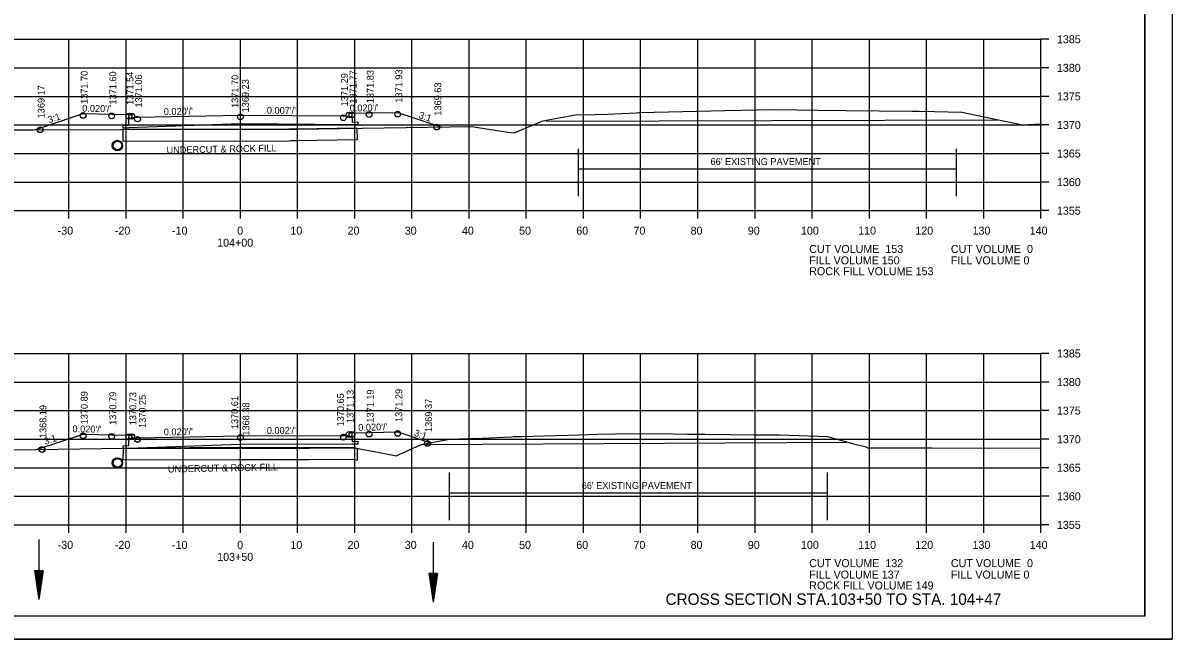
# Model space of a CAD drawing. Extents: x 1374311 to 1383814, y 384102 to 406278.
# Drawn here: x 1382682.8 to 1382883.8, y 385332.6 to 385440.4 of the extents above; entities that cross this region are included whole.
import ezdxf

# ---------------------------------------------------------------- set-up
doc = ezdxf.new("R2010")
doc.units = 0
for name, color, linetype in [('R_Axis', 7, 'Continuous'), ('R_Axis Annot', 7, 'Continuous'), ('R_Border', 7, 'Continuous'), ('R_Draft', 7, 'Continuous'), ('R_Exist Surface', 7, 'Continuous'), ('R_Fin Surface', 7, 'Continuous'), ('R_Grid', 7, 'Continuous'), ('R_No Plot', 7, 'Continuous'), ('R_Water', 7, 'Continuous'), ('R_Xsect Elev', 7, 'Continuous'), ('R_Xsect Slope', 7, 'Continuous')]:
    doc.layers.add(name, color=color, linetype=linetype)

msp = doc.modelspace()

# ---------------------------------------------------------------- linework, layer by layer
at = {"layer": 'R_Axis'}
for p, q in [((1382860.86, 385407.55), (1382860.86, 385437.55)), ((1382862.26, 385437.55), (1382860.86, 385437.55)), ((1382862.26, 385432.55), (1382860.86, 385432.55)), ((1382862.26, 385427.55), (1382860.86, 385427.55)), ((1382862.26, 385422.55), (1382860.86, 385422.55)), ((1382862.26, 385417.55), (1382860.86, 385417.55)), ((1382862.26, 385412.55), (1382860.86, 385412.55)), ((1382580.86, 385407.55), (1382860.86, 385407.55)), ((1382690.86, 385406.15), (1382690.86, 385407.55)), ((1382700.86, 385406.15), (1382700.86, 385407.55)), ((1382710.86, 385406.15), (1382710.86, 385407.55)), ((1382720.86, 385406.15), (1382720.86, 385407.55)), ((1382730.86, 385406.15), (1382730.86, 385407.55)), ((1382740.86, 385406.15), (1382740.86, 385407.55)), ((1382750.86, 385406.15), (1382750.86, 385407.55)), ((1382760.86, 385406.15), (1382760.86, 385407.55)), ((1382770.86, 385406.15), (1382770.86, 385407.55)), ((1382780.86, 385406.15), (1382780.86, 385407.55)), ((1382790.86, 385406.15), (1382790.86, 385407.55)), ((1382800.86, 385406.15), (1382800.86, 385407.55)), ((1382810.86, 385406.15), (1382810.86, 385407.55)), ((1382820.86, 385406.15), (1382820.86, 385407.55)), ((1382830.86, 385406.15), (1382830.86, 385407.55)), ((1382840.86, 385406.15), (1382840.86, 385407.55)), ((1382850.86, 385406.15), (1382850.86, 385407.55)), ((1382860.86, 385406.15), (1382860.86, 385407.55)), ((1382862.26, 385407.55), (1382860.86, 385407.55)), ((1382860.86, 385352.55), (1382860.86, 385382.55)), ((1382862.26, 385382.55), (1382860.86, 385382.55)), ((1382862.26, 385377.55), (1382860.86, 385377.55)), ((1382862.26, 385372.55), (1382860.86, 385372.55)), ((1382862.26, 385367.55), (1382860.86, 385367.55)), ((1382862.26, 385362.55), (1382860.86, 385362.55)), ((1382862.26, 385357.55), (1382860.86, 385357.55)), ((1382580.86, 385352.55), (1382860.86, 385352.55)), ((1382690.86, 385351.15), (1382690.86, 385352.55)), ((1382700.86, 385351.15), (1382700.86, 385352.55)), ((1382710.86, 385351.15), (1382710.86, 385352.55)), ((1382720.86, 385351.15), (1382720.86, 385352.55)), ((1382730.86, 385351.15), (1382730.86, 385352.55)), ((1382740.86, 385351.15), (1382740.86, 385352.55)), ((1382750.86, 385351.15), (1382750.86, 385352.55)), ((1382760.86, 385351.15), (1382760.86, 385352.55)), ((1382770.86, 385351.15), (1382770.86, 385352.55)), ((1382780.86, 385351.15), (1382780.86, 385352.55)), ((1382790.86, 385351.15), (1382790.86, 385352.55)), ((1382800.86, 385351.15), (1382800.86, 385352.55)), ((1382810.86, 385351.15), (1382810.86, 385352.55)), ((1382820.86, 385351.15), (1382820.86, 385352.55)), ((1382830.86, 385351.15), (1382830.86, 385352.55)), ((1382840.86, 385351.15), (1382840.86, 385352.55)), ((1382850.86, 385351.15), (1382850.86, 385352.55)), ((1382860.86, 385351.15), (1382860.86, 385352.55)), ((1382862.26, 385352.55), (1382860.86, 385352.55))]:
    msp.add_line(p, q, dxfattribs=at)
at = {"layer": 'R_Border'}
for q in [(1382879.04, 385542.01), (1382562.86, 385336.55)]:
    msp.add_line((1382879.04, 385336.55), q, dxfattribs=at)
at = {"layer": 'R_Draft'}
for p, q in [((1382684.84, 385344.5), (1382685.59, 385339.5)), ((1382686.34, 385344.5), (1382684.84, 385344.5)), ((1382684.97, 385344.5), (1382685.59, 385340.34)), ((1382685.1, 385344.5), (1382685.59, 385341.2)), ((1382685.22, 385344.5), (1382685.59, 385342.03)), ((1382685.35, 385344.5), (1382685.59, 385342.88)), ((1382685.48, 385344.5), (1382685.59, 385343.71)), ((1382686.34, 385344.5), (1382685.59, 385339.5)), ((1382685.84, 385344.5), (1382685.59, 385342.88)), ((1382686.09, 385344.5), (1382685.59, 385341.2)), ((1382686.22, 385344.5), (1382685.59, 385340.34)), ((1382685.97, 385344.5), (1382685.59, 385342.03)), ((1382685.71, 385344.5), (1382685.59, 385343.71)), ((1382753.83, 385344.03), (1382754.58, 385339.03)), ((1382755.33, 385344.03), (1382753.83, 385344.03)), ((1382753.96, 385344.03), (1382754.58, 385339.86)), ((1382754.09, 385344.03), (1382754.58, 385340.72)), ((1382754.21, 385344.03), (1382754.58, 385341.56)), ((1382754.34, 385344.03), (1382754.58, 385342.4)), ((1382754.47, 385344.03), (1382754.58, 385343.24)), ((1382755.33, 385344.03), (1382754.58, 385339.03)), ((1382754.83, 385344.03), (1382754.58, 385342.4)), ((1382755.08, 385344.03), (1382754.58, 385340.72)), ((1382755.21, 385344.03), (1382754.58, 385339.86)), ((1382754.96, 385344.03), (1382754.58, 385341.56)), ((1382754.7, 385344.03), (1382754.58, 385343.24))]:
    msp.add_line(p, q, dxfattribs=at)
at = {"layer": 'R_Exist Surface'}
for points in [[(1382669.63, 385421.71), (1382684.55, 385421.72), (1382699.89, 385421.74), (1382729.33, 385421.8), (1382729.62, 385421.81), (1382730.65, 385421.83), (1382761.33, 385422.27), (1382767.64, 385421.3), (1382768.72, 385421.17), (1382773.37, 385423.11), (1382773.77, 385423.29), (1382774.35, 385423.4), (1382779.44, 385424.32), (1382782.88, 385424.39), (1382785.08, 385424.46), (1382790.09, 385424.69), (1382790.56, 385424.71), (1382790.75, 385424.72), (1382805.57, 385425.1), (1382808.37, 385425.14), (1382813.91, 385425.23), (1382818.32, 385425.18), (1382821.86, 385425.13), (1382826.79, 385425.09), (1382838.29, 385424.97), (1382839.55, 385424.94), (1382842.28, 385424.89), (1382847.03, 385424.81), (1382853.45, 385423.46), (1382857.63, 385422.56), (1382860.86, 385422.74)], [(1382665.82, 385365.44), (1382692.76, 385365.84), (1382700.33, 385365.95), (1382711.04, 385365.98), (1382725.06, 385365.92), (1382740.83, 385366.03), (1382745.16, 385365.21), (1382748.12, 385364.66), (1382751.71, 385366.25), (1382752.52, 385366.6), (1382753.08, 385366.72), (1382757.45, 385367.58), (1382760.87, 385367.68), (1382763.13, 385367.75), (1382768.32, 385367.99), (1382768.6, 385368), (1382768.99, 385368.01), (1382770.07, 385368.04), (1382780.06, 385368.33), (1382783.33, 385368.42), (1382786.47, 385368.46), (1382791.39, 385368.53), (1382796.54, 385368.48), (1382799.05, 385368.45), (1382802.14, 385368.42), (1382810.69, 385368.34), (1382813.97, 385368.31), (1382815.15, 385368.29), (1382816.85, 385368.24), (1382823.56, 385368.04), (1382827.93, 385366.79), (1382830.32, 385366.21), (1382830.58, 385366.02), (1382832.09, 385366.04), (1382833.45, 385366.03), (1382841.84, 385366.02), (1382860.86, 385365.99)]]:
    msp.add_lwpolyline(points, dxfattribs=at)
for centre in [(1382699.35, 385418.95), (1382699.35, 385363.39)]:
    msp.add_circle(centre, 0.917, dxfattribs=at)
at = {"layer": 'R_Fin Surface'}
msp.add_line((1382741.31, 385421.98), (1382730.65, 385421.83), dxfattribs=at)
for points in [[(1382684.9, 385421.72), (1382693.35, 385424.53), (1382698.35, 385424.43), (1382701.35, 385424.37), (1382701.85, 385424.37), (1382701.86, 385423.87), (1382702.86, 385423.89), (1382720.86, 385424.25), (1382738.86, 385424.12), (1382739.86, 385424.1), (1382739.87, 385424.6), (1382740.37, 385424.6), (1382743.37, 385424.66), (1382748.37, 385424.76), (1382756.08, 385422.19)], [(1382740.37, 385424.3), (1382740.38, 385423.06), (1382741.38, 385423.08), (1382741.37, 385422.58), (1382740.37, 385422.59), (1382720.86, 385422.73), (1382701.35, 385422.03), (1382700.35, 385422), (1382700.36, 385422.5), (1382701.36, 385422.51), (1382701.35, 385424.07)], [(1382700.31, 385421.74), (1382700.31, 385419.74), (1382729.34, 385419.8), (1382729.65, 385419.81), (1382730.68, 385419.83), (1382741.32, 385419.98), (1382741.31, 385421.98)], [(1382700.31, 385421.74), (1382700.31, 385419.74), (1382729.34, 385419.8), (1382729.65, 385419.81), (1382730.68, 385419.83), (1382741.32, 385419.98), (1382741.31, 385421.98)], [(1382730.65, 385421.83), (1382729.62, 385421.81), (1382729.33, 385421.8), (1382700.31, 385421.74)], [(1382685.21, 385365.73), (1382693.35, 385368.44), (1382698.35, 385368.34), (1382701.35, 385368.28), (1382701.85, 385368.28), (1382701.86, 385367.78), (1382702.86, 385367.8), (1382720.86, 385368.16), (1382738.86, 385368.2), (1382739.86, 385368.18), (1382739.87, 385368.68), (1382740.37, 385368.68), (1382743.37, 385368.74), (1382748.37, 385368.84), (1382754.13, 385366.92)], [(1382740.37, 385368.38), (1382740.38, 385367.16), (1382741.38, 385367.18), (1382741.37, 385366.68), (1382740.37, 385366.68), (1382720.86, 385366.63), (1382701.35, 385365.94), (1382700.35, 385365.9), (1382700.36, 385366.4), (1382701.36, 385366.42), (1382701.35, 385367.97)], [(1382700.35, 385365.95), (1382700.31, 385363.95), (1382711.04, 385363.98), (1382725.06, 385363.92), (1382740.65, 385364.03), (1382741.32, 385363.9), (1382741.35, 385365.87)]]:
    msp.add_lwpolyline(points, dxfattribs=at)
msp.add_lwpolyline([(1382700.35, 385365.9), (1382700.31, 385363.95), (1382740.65, 385364.03), (1382741.32, 385363.9), (1382741.35, 385365.87), (1382740.83, 385366.03), (1382712.01, 385366.06), (1382700.35, 385365.9)], close=True, dxfattribs=at)
at = {"layer": 'R_Grid'}
for p, q in [((1382580.86, 385437.55), (1382860.86, 385437.55)), ((1382690.86, 385407.55), (1382690.86, 385437.55)), ((1382700.86, 385407.55), (1382700.86, 385437.55)), ((1382710.86, 385407.55), (1382710.86, 385437.55)), ((1382720.86, 385407.55), (1382720.86, 385437.55)), ((1382730.86, 385407.55), (1382730.86, 385437.55)), ((1382740.86, 385407.55), (1382740.86, 385437.55)), ((1382750.86, 385407.55), (1382750.86, 385437.55)), ((1382760.86, 385407.55), (1382760.86, 385437.55)), ((1382770.86, 385407.55), (1382770.86, 385437.55)), ((1382780.86, 385407.55), (1382780.86, 385437.55)), ((1382790.86, 385407.55), (1382790.86, 385437.55)), ((1382800.86, 385407.55), (1382800.86, 385437.55)), ((1382810.86, 385407.55), (1382810.86, 385437.55)), ((1382820.86, 385407.55), (1382820.86, 385437.55)), ((1382830.86, 385407.55), (1382830.86, 385437.55)), ((1382840.86, 385407.55), (1382840.86, 385437.55)), ((1382850.86, 385407.55), (1382850.86, 385437.55)), ((1382860.86, 385407.55), (1382860.86, 385437.55)), ((1382580.86, 385432.55), (1382860.86, 385432.55)), ((1382580.86, 385427.55), (1382860.86, 385427.55)), ((1382580.86, 385422.55), (1382860.86, 385422.55)), ((1382580.86, 385417.55), (1382860.86, 385417.55)), ((1382580.86, 385412.55), (1382860.86, 385412.55)), ((1382580.86, 385407.55), (1382860.86, 385407.55)), ((1382580.86, 385382.55), (1382860.86, 385382.55)), ((1382690.86, 385352.55), (1382690.86, 385382.55)), ((1382700.86, 385352.55), (1382700.86, 385382.55)), ((1382710.86, 385352.55), (1382710.86, 385382.55)), ((1382720.86, 385352.55), (1382720.86, 385382.55)), ((1382730.86, 385352.55), (1382730.86, 385382.55)), ((1382740.86, 385352.55), (1382740.86, 385382.55)), ((1382750.86, 385352.55), (1382750.86, 385382.55)), ((1382760.86, 385352.55), (1382760.86, 385382.55)), ((1382770.86, 385352.55), (1382770.86, 385382.55)), ((1382780.86, 385352.55), (1382780.86, 385382.55)), ((1382790.86, 385352.55), (1382790.86, 385382.55)), ((1382800.86, 385352.55), (1382800.86, 385382.55)), ((1382810.86, 385352.55), (1382810.86, 385382.55)), ((1382820.86, 385352.55), (1382820.86, 385382.55)), ((1382830.86, 385352.55), (1382830.86, 385382.55)), ((1382840.86, 385352.55), (1382840.86, 385382.55)), ((1382850.86, 385352.55), (1382850.86, 385382.55)), ((1382860.86, 385352.55), (1382860.86, 385382.55)), ((1382580.86, 385377.55), (1382860.86, 385377.55)), ((1382580.86, 385372.55), (1382860.86, 385372.55)), ((1382580.86, 385367.55), (1382860.86, 385367.55)), ((1382580.86, 385362.55), (1382860.86, 385362.55)), ((1382580.86, 385357.55), (1382860.86, 385357.55)), ((1382580.86, 385352.55), (1382860.86, 385352.55))]:
    msp.add_line(p, q, dxfattribs=at)
at = {"layer": 'R_No Plot'}
msp.add_line((1382550.46, 385332.57), (1382883.79, 385332.57), dxfattribs=at)
for points in [[(1382550.45, 385545.91), (1382883.79, 385545.91), (1382883.79, 385332.57), (1382550.45, 385332.57)], [(1382796.78, 385542.01), (1382796.78, 385532.13), (1382832.51, 385532.13), (1382832.51, 385529.21), (1382855.71, 385529.21), (1382855.71, 385506), (1382879.04, 385506), (1382879.04, 385336.55), (1382562.86, 385336.55), (1382562.86, 385542.01)], [(1382700.35, 385365.9), (1382700.35, 385365.95), (1382701.76, 385365.95), (1382701.35, 385365.94)]]:
    msp.add_lwpolyline(points, close=True, dxfattribs=at)
for centre in [(1382693.35, 385424.23), (1382693.35, 385424.23), (1382698.35, 385424.13), (1382698.35, 385424.13), (1382739.87, 385424.3), (1382739.87, 385424.3), (1382740.37, 385424.3), (1382743.37, 385424.36), (1382743.37, 385424.36), (1382748.37, 385424.46), (1382748.37, 385424.46), (1382701.35, 385424.07), (1382701.85, 385424.07), (1382701.85, 385424.07), (1382702.86, 385423.59), (1382702.86, 385423.59), (1382720.86, 385423.95), (1382720.86, 385423.95), (1382738.86, 385423.82), (1382738.86, 385423.82), (1382755.2, 385422.18), (1382755.21, 385422.18), (1382685.82, 385421.72), (1382685.82, 385421.72), (1382685.82, 385421.72), (1382685.82, 385421.72), (1382693.35, 385368.15), (1382693.35, 385368.13), (1382698.35, 385368.05), (1382698.35, 385368.03), (1382701.35, 385367.97), (1382701.85, 385367.99), (1382701.85, 385367.97), (1382720.86, 385367.87), (1382738.86, 385367.91), (1382738.86, 385367.9), (1382739.87, 385368.39), (1382739.87, 385368.38), (1382740.37, 385368.38), (1382743.37, 385368.45), (1382743.37, 385368.44), (1382748.37, 385368.55), (1382748.37, 385368.54), (1382702.86, 385367.51), (1382702.86, 385367.49), (1382720.86, 385367.85), (1382753.56, 385366.81), (1382753.58, 385366.81), (1382686.13, 385365.74), (1382686.13, 385365.74), (1382686.17, 385365.74), (1382686.17, 385365.74)]:
    msp.add_circle(centre, 0.5, dxfattribs=at)
at = {"layer": 'R_Water'}
for p, q in [((1382774.31, 385423.23), (1382853.28, 385423.43)), ((1382779.98, 385410.07), (1382779.98, 385418.4)), ((1382846.08, 385410.07), (1382846.08, 385418.4)), ((1382779.98, 385414.87), (1382846.08, 385414.87)), ((1382752.52, 385366.6), (1382826.9, 385367.04)), ((1382757.45, 385353.38), (1382757.45, 385361.7)), ((1382823.56, 385353.38), (1382823.56, 385361.7)), ((1382757.45, 385358.17), (1382823.56, 385358.17)), ((1382685.59, 385350.01), (1382685.59, 385339.5)), ((1382754.58, 385349.54), (1382754.58, 385339.03))]:
    msp.add_line(p, q, dxfattribs=at)
for centre in [(1382699.35, 385418.95), (1382699.35, 385363.39)]:
    msp.add_circle(centre, 0.75, dxfattribs=at)

# ---------------------------------------------------------------- texts
at = {"layer": 'R_Axis Annot'}
for s, p in [('1385', (1382863.66, 385436.85)), ('1380', (1382863.66, 385431.85)), ('1375', (1382863.66, 385426.85)), ('1370', (1382863.66, 385421.85)), ('1365', (1382863.66, 385416.85)), ('1360', (1382863.66, 385411.85)), ('1355', (1382863.66, 385406.85)), ('-30', (1382688.9, 385403.35)), ('-20', (1382698.9, 385403.35)), ('-10', (1382708.9, 385403.35)), ('0', (1382720.3, 385403.35)), ('10', (1382729.6, 385403.35)), ('20', (1382739.6, 385403.35)), ('30', (1382749.6, 385403.35)), ('40', (1382759.6, 385403.35)), ('50', (1382769.6, 385403.35)), ('60', (1382779.6, 385403.35)), ('70', (1382789.6, 385403.35)), ('80', (1382799.6, 385403.35)), ('90', (1382809.6, 385403.35)), ('100', (1382818.9, 385403.35)), ('110', (1382828.9, 385403.35)), ('120', (1382838.9, 385403.35)), ('130', (1382848.9, 385403.35)), ('140', (1382858.9, 385403.35)), ('104+00', (1382716.8, 385401.25)), ('CUT VOLUME  153', (1382820.34, 385400.15)), ('CUT VOLUME  0', (1382845.12, 385400.15)), ('FILL VOLUME 150', (1382820.34, 385398.15)), ('FILL VOLUME 0', (1382845.12, 385398.15)), ('ROCK FILL VOLUME 153', (1382820.34, 385396.25)), ('1385', (1382863.66, 385381.85)), ('1380', (1382863.66, 385376.85)), ('1375', (1382863.66, 385371.85)), ('1370', (1382863.66, 385366.85)), ('1365', (1382863.66, 385361.85)), ('1360', (1382863.66, 385356.85)), ('1355', (1382863.66, 385351.85)), ('-30', (1382688.9, 385348.35)), ('-20', (1382698.9, 385348.35)), ('-10', (1382708.9, 385348.35)), ('0', (1382720.3, 385348.35)), ('10', (1382729.6, 385348.35)), ('20', (1382739.6, 385348.35)), ('30', (1382749.6, 385348.35)), ('40', (1382759.6, 385348.35)), ('50', (1382769.6, 385348.35)), ('60', (1382779.6, 385348.35)), ('70', (1382789.6, 385348.35)), ('80', (1382799.6, 385348.35)), ('90', (1382809.6, 385348.35)), ('100', (1382818.9, 385348.35)), ('110', (1382828.9, 385348.35)), ('120', (1382838.9, 385348.35)), ('130', (1382848.9, 385348.35)), ('140', (1382858.9, 385348.35)), ('103+50', (1382716.8, 385346.25)), ('CUT VOLUME  132', (1382820.34, 385345.15)), ('CUT VOLUME  0', (1382845.12, 385345.15)), ('FILL VOLUME 137', (1382820.34, 385343.15)), ('FILL VOLUME 0', (1382845.12, 385343.15)), ('ROCK FILL VOLUME 149', (1382820.34, 385341.25))]:
    msp.add_text(s, height=1.4, dxfattribs=at).set_placement(p)
at = {"layer": 'R_Draft'}
msp.add_text('CROSS SECTION STA.103+50 TO STA. 104+47', height=2, dxfattribs=at).set_placement((1382795.21, 385338.55))
at = {"layer": 'R_Fin Surface'}
for p in [(1382707.95, 385417.54), (1382708.19, 385361.71)]:
    msp.add_text('UNDERCUT & ROCK FILL', height=1.2, rotation=1.1458, dxfattribs=at).set_placement(p)
at = {"layer": 'R_Water'}
for p in [(1382803.08, 385415.54), (1382780.55, 385358.84)]:
    msp.add_text("66' EXISTING PAVEMENT", height=1.2, dxfattribs=at).set_placement(p)
at = {"layer": 'R_Xsect Elev'}
for s, p in [('1371.70', (1382694.15, 385426.23)), ('1371.60', (1382699.15, 385426.13)), ('1371.54', (1382702.15, 385426.07)), ('1371.06', (1382703.66, 385425.59)), ('1371.70', (1382720.51, 385425.53)), ('1371.29', (1382739.66, 385425.82)), ('1371.77', (1382741.17, 385426.3)), ('1371.83', (1382744.17, 385426.36)), ('1371.93', (1382749.17, 385426.46)), ('1369.17', (1382686.62, 385423.72)), ('1369.23', (1382722.34, 385424.76)), ('1369.63', (1382756, 385424.18)), ('1370.89', (1382694.15, 385370.15)), ('1370.79', (1382699.15, 385370.05)), ('1370.73', (1382702.65, 385369.99)), ('1370.25', (1382704.31, 385369.51)), ('1370.61', (1382720.47, 385369.31)), ('1370.65', (1382738.97, 385369.78)), ('1371.13', (1382740.67, 385370.39)), ('1371.19', (1382744.17, 385370.45)), ('1371.29', (1382749.17, 385370.55)), ('1369.37', (1382754.38, 385368.81)), ('1368.19', (1382686.93, 385367.74)), ('1368.38', (1382722.43, 385368.17))]:
    msp.add_text(s, height=1.2, rotation=90, dxfattribs=at).set_placement(p)
at = {"layer": 'R_Xsect Slope'}
for s, rotation, p in [("0.020'/'", 358.8542, (1382693.19, 385424.89)), ("0.020'/'", 1.1458, (1382707.47, 385424.28)), ("0.007'/'", 359.5889, (1382725.49, 385424.52)), ("0.020'/'", 1.1458, (1382739.98, 385424.89)), ('3:1', 341.5651, (1382751.95, 385423.8)), ('3:1', 18.4349, (1382687.38, 385422.84)), ("0.020'/'", 1.1458, (1382741.48, 385369.01)), ("0.020'/'", 358.8542, (1382691.48, 385368.78)), ("0.020'/'", 1.1458, (1382707.47, 385368.2)), ("0.002'/'", 0.1373, (1382725.48, 385368.48)), ('3:1', 341.5651, (1382751.13, 385368.16)), ('3:1', 18.4349, (1382686.72, 385366.54))]:
    msp.add_text(s, height=1.2, rotation=rotation, dxfattribs=at).set_placement(p)

doc.saveas('drawing.dxf')
